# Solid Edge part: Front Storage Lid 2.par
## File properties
Username: m_hel
Author: m_hel
Template: Iso Metric Part.par
Last saved by: m_hel
Revision: 9
Application: Solid Edge
Accuracy: 0,990
Material: Textured White
Face Style: White painted
Fill Style: ANSI36(Marble)
Virtual Style: ANSI36(Marble)
Grouping: Uncategorized
LibraryName: Custom Materials
Coef. of Thermal Exp: 0.0
Thermal Conductivity: 0.0
Specific Heat: 0.0
Modulus of Elasticity: 0.0
Poisson's Ratio: 0.0
Yield Stress: 0.0
Ultimate Stress: 0.0
Elongation: 0.0
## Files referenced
..\..\Redfisher18.asm
G:\OneDriveTemp\OneDrive\Dokumendid\TLÜ tööd\3D Modelleerimine\3d modelling\veesõiduk\Deck1.par
iduk\Deck1.par
iduk\Redfisher18.asm
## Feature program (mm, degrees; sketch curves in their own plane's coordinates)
sketch for "unnamed Protrusion 1" plane through (0, 0, 70) normal (0, 0, 1) x-axis (1, 0, 0)
  line (-616.4775, 1120) -> (616.4775, 1120)
  arc centre (-2833.7179, -36.0362) radius 3638.7179 from (616.4775, 1120) to (380.2685, 1670) ccw
  line (380.2685, 1670) -> (-380.2685, 1670)
  arc centre (2833.7179, -36.0362) radius 3638.7179 from (-380.2685, 1670) to (-616.4775, 1120) ccw
extrude "unnamed Protrusion 1" add finite 50 along -normal
fillet "Round_1" radius 20
thinwall "Thinwall_1"  Thickness = 10 mm
sketch for "unnamed Cutout 1" plane through (0, 1395, 70) normal (0, 0, 1) x-axis (1, 0, 0)
  circle centre (0, -175) radius 35
extrude "unnamed Cutout 1" cut through along -normal
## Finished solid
Body 1: solid body, 36 faces, 74 edges, 40 vertices.
  Faces by surface: cylinder 17, sphere 8, plane 7, torus 4
  Edges by curve: circle 46, line 28
Bounding box of the edges (mm; curved faces can reach further): 1217.141 x 550.000 x 50.000, from (-608.5705, 1120, 20) to (608.5705, 1670, 70).
Cylindrical faces by radius (mm): R10 x6, R20 x6, R35 x1, R3628.7179 x2, R3638.7179 x2
Toroidal faces (ring radius, tube radius in mm): R3618.7179 r10 x2, R3618.7179 r20 x2
Spherical faces by radius (mm): R10 x4, R20 x4
Planar faces by outward normal: +y 2, +z 1, -y 2, -z 2
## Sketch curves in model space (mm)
circle centre (0, 1220, 70) radius 35
line (-616.4775, 1120, 70) -> (616.4775, 1120, 70)
arc centre (-2833.7179, -36.0362, 70) radius 3638.7179 from (616.4775, 1120, 70) through (509.7017, 1399.8654, 70) to (380.2685, 1670, 70)
line (380.2685, 1670, 70) -> (-380.2685, 1670, 70)
arc centre (2833.7179, -36.0362, 70) radius 3638.7179 from (-380.2685, 1670, 70) through (-509.7017, 1399.8654, 70) to (-616.4775, 1120, 70)
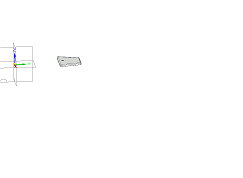
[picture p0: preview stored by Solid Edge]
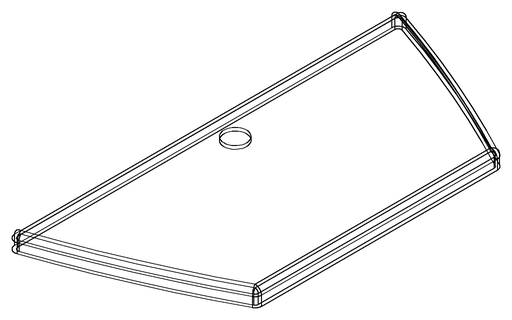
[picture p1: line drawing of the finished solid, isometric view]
